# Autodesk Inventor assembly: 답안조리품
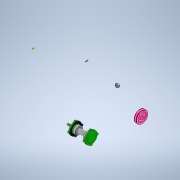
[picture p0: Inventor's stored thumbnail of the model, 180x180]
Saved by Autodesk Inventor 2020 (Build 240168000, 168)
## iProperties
Created: 2022-11
Part Number: 답안조리품
Document SubType Name: Assembly
Designer: owner
Author: owner
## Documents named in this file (12)
- C:\Users\owner\Desktop\721108V1002\답안조리품.iam
- C:\Users\owner\Desktop\721108V1002\본체.ipt
- C:\Users\owner\Desktop\721108V1002\V-벨트풀리.ipt
- C:\Users\owner\Desktop\721108V1002\개스킷.ipt
- C:\Users\owner\Desktop\721108V1002\너트 M12 x 1.25.ipt
- C:\Users\owner\Desktop\721108V1002\뒤커버.ipt
- C:\Users\owner\Desktop\721108V1002\베어링 6204.ipt
- C:\Users\owner\Desktop\721108V1002\볼트 M4 x 12.ipt
- C:\Users\owner\Desktop\721108V1002\앞커버.ipt
- C:\Users\owner\Desktop\721108V1002\오일 실.ipt
- C:\Users\owner\Desktop\721108V1002\축.ipt
- C:\Users\owner\Desktop\721108V1002\키 4 x 4.ipt
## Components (8 placed, 6 different names)
1. V-벨트풀리:1
2. 개스킷:1
3. KS B 1012 클래스 1 일반 - 미터 M12x1.25:1
4. KS B 2023 6204 - 20 x 47 x 14:1
5. KS B 2804 D D - 20 32 8:1
6. KS B 1311 (I) 4 x 4 x 12:1
7. 개스킷:2
8. KS B 2023 6204 - 20 x 47 x 14:2
